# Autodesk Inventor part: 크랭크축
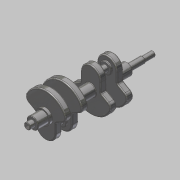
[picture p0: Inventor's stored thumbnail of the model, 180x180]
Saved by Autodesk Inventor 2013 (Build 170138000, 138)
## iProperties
Created: 2017-03
Part Number: 크랭크축
Material: 강철, 탄소
Document SubType Name: Modeling
Designer: mduedu
Density: 7.87 g/cm^3
Mass: 2638.48 g
Surface Area: 631.346 cm^2
Volume: 335.258 cm^3
Author: mduedu
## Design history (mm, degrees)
sketch "스케치1" dims "d5" = 57
  geometry: L1 (-19, 21.243)-(-19, 3.243); L2 (-19, 3.243)-(-40.023, -8.895); L3 (19, 21.243)-(19, 3.243); L4 (0, 21.243)-(0, -41); L5 (19, 3.243)-(40.023, -8.895); C1 r 6 at (0, 0); C2 r 13.5 at (0, 0); A1 r 41 centre (0, 0) between (-40.023, -8.895) and (0, -41); A2 r 41 centre (0, 0) between (0, -41) and (40.023, -8.895); A3 r 19 centre (0, 21.243) between (19, 21.243) and (0, 40.243); A4 r 19 centre (0, 21.243) between (0, 40.243) and (-19, 21.243); 3 further points
  constraints: 10 end point, 8 point on circle, 6 centre point, 5 coincident, 3 symmetric about line, 2 point on line, 1 parallel, 1 tangent, 1 vertical, 1 vertical alignment, 5 other
  dimensions: "d0" = 12 diameter of C1; "d1" = 27 diameter of C2; "d2" = 18 distance of L1.start L1.end; "d3" = 120 deg angle of L2 L1; "d4" = 41 radius of A1; "d6" = 19 radius of A4
extrude "돌출1" new body sketch "스케치1" distance "d7" = 12; taper "d8" = 0 deg
extrude "돌출2" join sketch "스케치1" distance "d9" = 5; taper "d10" = 0 deg
extrude "돌출3" join sketch "스케치1" distance "d11" = 75; taper "d12" = 0 deg
sketch "스케치2"
  geometry: C1 r 11 at (0, 21.243); C2 r 6 at (0, 21.243); A1 r 19 centre (0, 21.243) between (19, 21.243) and (-19, 21.243) reference; 1 further point
  constraints: 2 centre point, 2 coincident
  dimensions: "d13" = 22 diameter of C1; "d14" = 12 diameter of C2
extrude "돌출4" join sketch "스케치2" distance "d15" = 3; taper "d16" = 0 deg
extrude "돌출5" join sketch "스케치2" distance "d17" = 16; taper "d18" = 0 deg
fillet "모깎기1" dims "d19" = 3, "d20" = 10
fillet "모깎기2" dims "d21" = 2
sketch "스케치3"
  geometry: C1 r 11 at (0, 0); 1 further point
  constraints: 1 centre point, 1 coincident
  dimensions: "d22" = 22 diameter of C1
extrude "돌출6" join sketch "스케치3" distance "d23" = 21; taper "d24" = 0 deg
sketch "스케치4"
  geometry: C1 r 6 at (0, 0) reference; C2 r 5 at (0, 0); 1 further point
  constraints: 1 centre point
  dimensions: "d25" = 1 radial gap between concentric circles of C1 C2
extrude "돌출7" cut sketch "스케치4" distance "d26" = 20; taper "d27" = 0 deg
node "작업 평면1"
sketch "스케치5"
  geometry: L1 (-5, 0)-(5, 0) reference; L2 (-1.5, 0)-(1.5, 0); L3 (1.5, 0)-(1.5, 8.5); L4 (-1.5, 8.5)-(-1.5, 0); A1 r 1.5 centre (0, 8.5) between (1.5, 8.5) and (-1.5, 8.5); 1 further point
  constraints: 6 end point, 2 point on circle, 2 tangent, 1 centre point, 1 horizontal, 1 parallel, 1 perpendicular, 1 point on line, 1 vertical alignment
  dimensions: "d28" = 3 distance between parallel lines of L3 L4; "d30" = 10 dimension on A1 L1
extrude "돌출8" cut sketch "스케치5" distance "d31" = 1.8; taper "d32" = 0 deg
chamfer "모따기1" distance "d33" = 1; stored, may be unused: second distance "d34" = 2, angle "d35" = 45 deg
chamfer "모따기2" distance "d36" = 1; stored, may be unused: second distance "d37" = 2, angle "d38" = 45 deg
node "작업 평면2"
sketch "스케치6"
  geometry: C1 r 11 at (0, 0) reference; C2 r 11 at (0, 0) reference; 1 further point
extrude "돌출9" join sketch "스케치6" distance "d39" = 42; taper "d40" = 0 deg
sketch "스케치7" dims "d46" = 57
  geometry: L1 (-19, -21.243)-(-19, -3.243); L2 (19, -21.243)-(19, -3.243); L3 (-19, -3.243)-(-40.023, 8.895); L4 (19, -3.243)-(40.023, 8.895); L5 (0, -21.243)-(0, 41); C1 r 13.5 at (0, 0); C2 r 6 at (0, 0); A1 r 19 centre (0, -21.243) between (0, -40.243) and (19, -21.243); A2 r 19 centre (0, -21.243) between (-19, -21.243) and (0, -40.243); A3 r 41 centre (0, 0) between (0, 41) and (-40.023, 8.895); A4 r 41 centre (0, 0) between (40.023, 8.895) and (0, 41); 3 further points
  constraints: 10 end point, 8 point on circle, 6 centre point, 5 coincident, 3 symmetric about line, 2 point on line, 1 parallel, 1 tangent, 1 vertical, 5 other
  dimensions: "d41" = 12 diameter of C2; "d42" = 27 diameter of C1; "d43" = 18 distance of L2.start L2.end; "d44" = 120 deg angle of L4 L2; "d45" = 41 radius of A4; "d47" = 19 radius of A1
extrude "돌출10" join sketch "스케치7" distance "d48" = 12; taper "d49" = 0 deg
sketch "스케치8"
  geometry: C1 r 11 at (0, -21.243); C2 r 6 at (0, -21.243); A1 r 19 centre (0, -21.243) between (-19, -21.243) and (19, -21.243) reference; 1 further point
  constraints: 2 centre point, 2 coincident
  dimensions: "d50" = 22 diameter of C1; "d51" = 12 diameter of C2
extrude "돌출11" join sketch "스케치8" distance "d52" = 3; taper "d53" = 0 deg
extrude "돌출12" join sketch "스케치8" distance "d54" = 16; taper "d55" = 0 deg
fillet "모깎기3" dims "d56" = 3, "d57" = 10
fillet "모깎기4" dims "d58" = 2
chamfer "모따기3" distance "d59" = 1; stored, may be unused: second distance "d60" = 2, angle "d61" = 45 deg
node "작업 평면3"
fillet "모깎기5" dims "d62" = 1
sketch "스케치9"
  geometry: C1 r 13.5 at (0, 0) reference; 1 further point
extrude "돌출13" join sketch "스케치9" distance "d63" = 5; taper "d64" = 0 deg
sketch "스케치10"
  geometry: C1 r 6 at (0, 0) reference; 1 further point
extrude "돌출14" join sketch "스케치10" distance "d65" = 30; taper "d66" = 0 deg
sketch "스케치11"
  geometry: C1 r 11 at (0, 0); 1 further point
  constraints: 1 centre point, 1 coincident
  dimensions: "d67" = 22 diameter of C1
extrude "돌출15" join sketch "스케치11" distance "d68" = 20; taper "d69" = 0 deg
chamfer "모따기4" distance "d70" = 1; stored, may be unused: second distance "d71" = 2, angle "d72" = 45 deg
chamfer "모따기5" distance "d75" = 0.7; stored, may be unused: second distance "d76" = 2, angle "d77" = 30 deg
fillet "모깎기6" dims "d78" = 0.3
node "솔리드1"
mirror "대칭1"
mirror "대칭2"
node "투영된 루프1"
